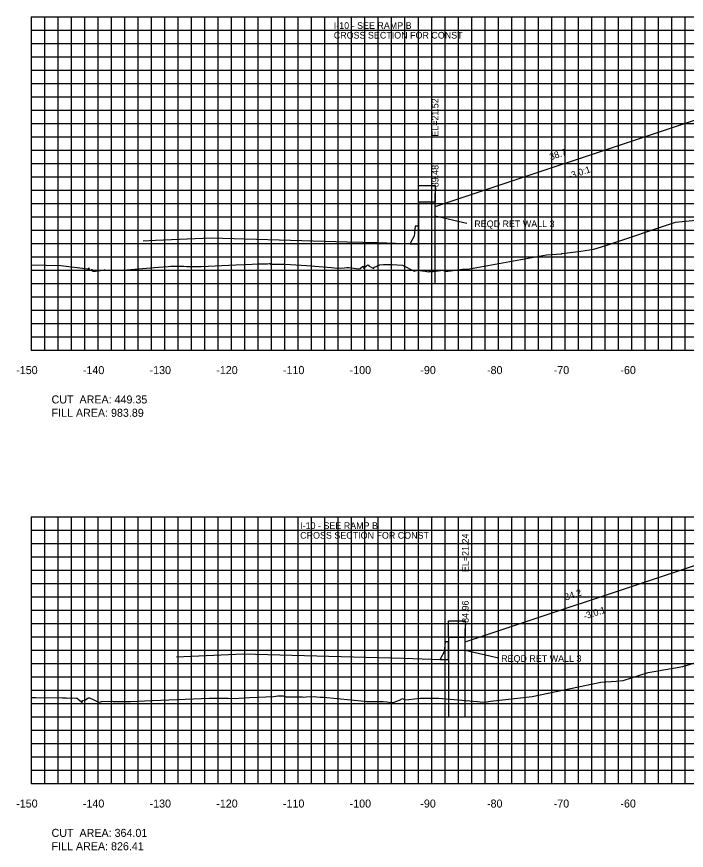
# Model space of a CAD drawing. Extents: x 1800880 to 1814006, y 250083 to 250560.
# Drawn here: x 1808258.8 to 1808359.2, y 250089.4 to 250214.4 of the extents above; entities that cross this region are included whole.
import ezdxf

# ---------------------------------------------------------------- set-up
doc = ezdxf.new("R2010")
doc.units = 0
for name, color, linetype in [('ANNO-TXT', 7, 'Continuous'), ('CL-CNST', 7, 'Continuous'), ('Default', 7, 'Continuous'), ('DESIGN - DRAINAGE - Bridges', 7, 'Continuous'), ('DRAINAGETXT', 7, 'Continuous'), ('EPTEXT', 7, 'Continuous'), ('Level 37', 7, 'Continuous'), ('Level 46', 7, 'Continuous'), ('Level 62', 7, 'Continuous'), ('SHT-BDR', 7, 'Continuous')]:
    doc.layers.add(name, color=color, linetype=linetype)

msp = doc.modelspace()

# ---------------------------------------------------------------- linework, layer by layer
at = {"layer": 'CL-CNST'}
for points in [[(1808261, 250177.21), (1808265.39, 250177.13), (1808269.46, 250176.6), (1808269.6, 250176.52), (1808269.61, 250176.77), (1808269.64, 250176.5), (1808269.64, 250176.54), (1808269.67, 250176.5), (1808269.71, 250176.44), (1808269.73, 250176.42), (1808269.78, 250176.43), (1808269.84, 250176.42), (1808269.89, 250176.4), (1808269.93, 250176.38), (1808270.04, 250176.55), (1808270.09, 250176.28), (1808270.13, 250176.32), (1808270.14, 250176.32), (1808270.15, 250176.27), (1808270.17, 250176.28), (1808270.25, 250176.25), (1808270.43, 250176.28), (1808270.57, 250176.27), (1808271.67, 250176.43), (1808271.89, 250176.47), (1808272, 250176.45), (1808272.22, 250176.44), (1808272.42, 250176.42), (1808273.38, 250176.43), (1808274.69, 250176.44), (1808280.03, 250176.88), (1808281.49, 250176.99), (1808281.82, 250177), (1808283.86, 250177), (1808284.25, 250176.96), (1808284.27, 250176.96), (1808284.36, 250176.96), (1808286.45, 250176.99), (1808291.62, 250177.22), (1808294.07, 250177.33), (1808295.08, 250177.35), (1808296.36, 250177.36), (1808296.61, 250177.43), (1808296.76, 250177.43), (1808296.79, 250177.34), (1808297.6, 250177.34), (1808299.03, 250177.34), (1808302.24, 250177.11), (1808305.96, 250176.84), (1808306.81, 250176.72), (1808307.93, 250176.78), (1808308.29, 250176.83), (1808308.6, 250176.83), (1808309.02, 250176.76), (1808309.96, 250176.64), (1808310.3, 250176.68), (1808310.66, 250177.03), (1808310.89, 250176.79), (1808310.89, 250176.6), (1808310.9, 250176.8), (1808310.92, 250176.84), (1808310.92, 250176.84), (1808311.19, 250177.04), (1808311.29, 250177.12), (1808311.49, 250177.23), (1808311.59, 250177.05), (1808312.26, 250176.68), (1808312.44, 250176.89), (1808313.24, 250177.24), (1808313.78, 250177.26), (1808315.09, 250177.26), (1808316.64, 250177.19), (1808318.37, 250176.26), (1808318.87, 250176.43), (1808320.01, 250176.26), (1808320.25, 250176.21), (1808320.46, 250176.18), (1808320.62, 250176.2), (1808321.22, 250176.24), (1808321.63, 250176.27), (1808322.69, 250176.42), (1808322.97, 250176.28), (1808323.07, 250176.24), (1808325.63, 250176.57), (1808326.67, 250176.63), (1808338.24, 250178.72), (1808340.45, 250178.89), (1808340.5, 250178.92), (1808340.57, 250178.93), (1808343.37, 250179.29), (1808345.32, 250179.55), (1808347.14, 250180.1), (1808357.54, 250183.62), (1808361.13, 250183.99)], [(1808261, 250112.34), (1808261.65, 250112.33), (1808265.61, 250112.26), (1808266.15, 250112.26), (1808266.17, 250112.24), (1808266.82, 250112.27), (1808267.05, 250112.27), (1808267.1, 250112.27), (1808267.11, 250112.27), (1808267.5, 250112.24), (1808267.64, 250112.26), (1808267.75, 250112.25), (1808267.84, 250112.24), (1808267.95, 250112.15), (1808268.48, 250111.69), (1808268.61, 250111.49), (1808268.64, 250111.9), (1808269.07, 250111.99), (1808269.47, 250112.26), (1808269.69, 250112.26), (1808270.33, 250111.98), (1808270.85, 250111.74), (1808271.18, 250111.62), (1808271.5, 250111.72), (1808273.14, 250111.79), (1808273.26, 250111.75), (1808275.28, 250111.74), (1808275.86, 250111.74), (1808277.92, 250111.83), (1808286.49, 250112.19), (1808287.62, 250112.21), (1808288.73, 250112.22), (1808289.03, 250112.22), (1808290.47, 250112.21), (1808291.55, 250112.2), (1808292.1, 250112.23), (1808293.68, 250112.35), (1808297.32, 250112.48), (1808297.91, 250112.57), (1808298.68, 250112.59), (1808298.74, 250112.58), (1808299.2, 250112.41), (1808299.61, 250112.45), (1808301.6, 250112.43), (1808301.72, 250112.4), (1808302.17, 250112.42), (1808303.5, 250112.47), (1808303.77, 250112.42), (1808304.26, 250112.4), (1808304.77, 250112.4), (1808310.92, 250111.78), (1808311.23, 250111.74), (1808311.43, 250111.74), (1808311.65, 250111.74), (1808312.25, 250111.74), (1808313.75, 250111.74), (1808314.29, 250111.68), (1808314.65, 250111.65), (1808315, 250111.6), (1808315.38, 250111.65), (1808316.19, 250111.94), (1808316.61, 250112.19), (1808316.99, 250112), (1808317.6, 250112.01), (1808319.27, 250112.23), (1808320.19, 250112.23), (1808320.89, 250112.23), (1808322, 250112.25), (1808327.89, 250111.72), (1808328.26, 250111.7), (1808328.92, 250111.64), (1808329.8, 250111.8), (1808334.31, 250112.3), (1808336.08, 250112.5), (1808346.36, 250114.64), (1808348.65, 250114.8), (1808349.71, 250114.87), (1808353.44, 250116.07), (1808355.78, 250116.48), (1808358.66, 250116.98), (1808364.9, 250118.86)]]:
    msp.add_lwpolyline(points, dxfattribs=at)
at = {"layer": 'Default'}
for p, q in [((1808319.03, 250180.37), (1808319.03, 250183.04)), ((1808323.54, 250118.02), (1808323.54, 250120.69))]:
    msp.add_line(p, q, dxfattribs=at)
for points in [[(1808319.03, 250183.04), (1808318.53, 250183.04), (1808318.35, 250181.54), (1808317.8, 250180.54), (1808317.78, 250180.37), (1808319.03, 250180.37)], [(1808323.54, 250120.69), (1808323.04, 250120.69), (1808322.86, 250119.19), (1808322.31, 250118.19), (1808322.29, 250118.02), (1808323.54, 250118.02)]]:
    msp.add_lwpolyline(points, dxfattribs=at)
at = {"layer": 'DESIGN - DRAINAGE - Bridges'}
for p, q in [((1808260.94, 250214.43), (1808261, 250214.43)), ((1808261, 250164.43), (1808261, 250214.43)), ((1808260.94, 250204.43), (1808261, 250204.43)), ((1808260.94, 250194.43), (1808261, 250194.43)), ((1808260.94, 250184.43), (1808261, 250184.43)), ((1808260.94, 250174.43), (1808261, 250174.43)), ((1808260.94, 250164.43), (1808261, 250164.43)), ((1808261, 250164.43), (1808561, 250164.43)), ((1808261, 250164.37), (1808261, 250164.43)), ((1808271, 250164.37), (1808271, 250164.43)), ((1808281, 250164.37), (1808281, 250164.43)), ((1808291, 250164.37), (1808291, 250164.43)), ((1808301, 250164.37), (1808301, 250164.43)), ((1808311, 250164.37), (1808311, 250164.43)), ((1808321, 250164.37), (1808321, 250164.43)), ((1808331, 250164.37), (1808331, 250164.43)), ((1808341, 250164.37), (1808341, 250164.43)), ((1808351, 250164.37), (1808351, 250164.43)), ((1808260.94, 250139.43), (1808261, 250139.43)), ((1808261, 250099.43), (1808261, 250139.43)), ((1808260.94, 250129.43), (1808261, 250129.43)), ((1808260.94, 250119.43), (1808261, 250119.43)), ((1808260.94, 250109.43), (1808261, 250109.43)), ((1808260.94, 250099.43), (1808261, 250099.43)), ((1808261, 250099.43), (1808561, 250099.43)), ((1808261, 250099.37), (1808261, 250099.43)), ((1808271, 250099.37), (1808271, 250099.43)), ((1808281, 250099.37), (1808281, 250099.43)), ((1808291, 250099.37), (1808291, 250099.43)), ((1808301, 250099.37), (1808301, 250099.43)), ((1808311, 250099.37), (1808311, 250099.43)), ((1808321, 250099.37), (1808321, 250099.43)), ((1808331, 250099.37), (1808331, 250099.43)), ((1808341, 250099.37), (1808341, 250099.43)), ((1808351, 250099.37), (1808351, 250099.43))]:
    msp.add_line(p, q, dxfattribs=at)
at = {"layer": 'EPTEXT'}
for p, q in [((1808326.25, 250183.43), (1808321.53, 250184.53)), ((1808331.04, 250118.23), (1808326.04, 250119.4))]:
    msp.add_line(p, q, dxfattribs=at)
at = {"layer": 'Level 37'}
for p, q in [((1808321.52, 250185.96), (1808321.52, 250187.96)), ((1808326.04, 250120.67), (1808326.04, 250122.67))]:
    msp.add_line(p, q, dxfattribs=at)
at = {"layer": 'Level 46'}
for p, q in [((1808261, 250214.43), (1808561, 250214.43)), ((1808261, 250164.43), (1808261, 250214.43)), ((1808263, 250164.43), (1808263, 250214.43)), ((1808265, 250164.43), (1808265, 250214.43)), ((1808267, 250164.43), (1808267, 250214.43)), ((1808269, 250164.43), (1808269, 250214.43)), ((1808271, 250164.43), (1808271, 250214.43)), ((1808273, 250164.43), (1808273, 250214.43)), ((1808275, 250164.43), (1808275, 250214.43)), ((1808277, 250164.43), (1808277, 250214.43)), ((1808279, 250164.43), (1808279, 250214.43)), ((1808281, 250164.43), (1808281, 250214.43)), ((1808283, 250164.43), (1808283, 250214.43)), ((1808285, 250164.43), (1808285, 250214.43)), ((1808287, 250164.43), (1808287, 250214.43)), ((1808289, 250164.43), (1808289, 250214.43)), ((1808291, 250164.43), (1808291, 250214.43)), ((1808293, 250164.43), (1808293, 250214.43)), ((1808295, 250164.43), (1808295, 250214.43)), ((1808297, 250164.43), (1808297, 250214.43)), ((1808299, 250164.43), (1808299, 250214.43)), ((1808301, 250164.43), (1808301, 250214.43)), ((1808303, 250164.43), (1808303, 250214.43)), ((1808305, 250164.43), (1808305, 250214.43)), ((1808307, 250164.43), (1808307, 250214.43)), ((1808309, 250164.43), (1808309, 250214.43)), ((1808311, 250164.43), (1808311, 250214.43)), ((1808313, 250164.43), (1808313, 250214.43)), ((1808315, 250164.43), (1808315, 250214.43)), ((1808317, 250164.43), (1808317, 250214.43)), ((1808319, 250164.43), (1808319, 250214.43)), ((1808321, 250164.43), (1808321, 250214.43)), ((1808323, 250164.43), (1808323, 250214.43)), ((1808325, 250164.43), (1808325, 250214.43)), ((1808327, 250164.43), (1808327, 250214.43)), ((1808329, 250164.43), (1808329, 250214.43)), ((1808331, 250164.43), (1808331, 250214.43)), ((1808333, 250164.43), (1808333, 250214.43)), ((1808335, 250164.43), (1808335, 250214.43)), ((1808337, 250164.43), (1808337, 250214.43)), ((1808339, 250164.43), (1808339, 250214.43)), ((1808341, 250164.43), (1808341, 250214.43)), ((1808343, 250164.43), (1808343, 250214.43)), ((1808345, 250164.43), (1808345, 250214.43)), ((1808347, 250164.43), (1808347, 250214.43)), ((1808349, 250164.43), (1808349, 250214.43)), ((1808351, 250164.43), (1808351, 250214.43)), ((1808353, 250164.43), (1808353, 250214.43)), ((1808355, 250164.43), (1808355, 250214.43)), ((1808357, 250164.43), (1808357, 250214.43)), ((1808359, 250164.43), (1808359, 250214.43)), ((1808261, 250212.43), (1808561, 250212.43)), ((1808261, 250210.43), (1808561, 250210.43)), ((1808261, 250208.43), (1808561, 250208.43)), ((1808261, 250206.43), (1808561, 250206.43)), ((1808261, 250204.43), (1808561, 250204.43)), ((1808261, 250202.43), (1808561, 250202.43)), ((1808261, 250200.43), (1808561, 250200.43)), ((1808261, 250198.43), (1808561, 250198.43)), ((1808261, 250196.43), (1808561, 250196.43)), ((1808261, 250194.43), (1808561, 250194.43)), ((1808261, 250192.43), (1808561, 250192.43)), ((1808261, 250190.43), (1808561, 250190.43)), ((1808261, 250188.43), (1808561, 250188.43)), ((1808261, 250186.43), (1808561, 250186.43)), ((1808261, 250184.43), (1808561, 250184.43)), ((1808261, 250182.43), (1808561, 250182.43)), ((1808261, 250180.43), (1808561, 250180.43)), ((1808261, 250178.43), (1808561, 250178.43)), ((1808261, 250176.43), (1808561, 250176.43)), ((1808261, 250174.43), (1808561, 250174.43)), ((1808261, 250172.43), (1808561, 250172.43)), ((1808261, 250170.43), (1808561, 250170.43)), ((1808261, 250168.43), (1808561, 250168.43)), ((1808261, 250166.43), (1808561, 250166.43)), ((1808261, 250164.43), (1808561, 250164.43)), ((1808261, 250139.43), (1808561, 250139.43)), ((1808261, 250099.43), (1808261, 250139.43)), ((1808263, 250099.43), (1808263, 250139.43)), ((1808265, 250099.43), (1808265, 250139.43)), ((1808267, 250099.43), (1808267, 250139.43)), ((1808269, 250099.43), (1808269, 250139.43)), ((1808271, 250099.43), (1808271, 250139.43)), ((1808273, 250099.43), (1808273, 250139.43)), ((1808275, 250099.43), (1808275, 250139.43)), ((1808277, 250099.43), (1808277, 250139.43)), ((1808279, 250099.43), (1808279, 250139.43)), ((1808281, 250099.43), (1808281, 250139.43)), ((1808283, 250099.43), (1808283, 250139.43)), ((1808285, 250099.43), (1808285, 250139.43)), ((1808287, 250099.43), (1808287, 250139.43)), ((1808289, 250099.43), (1808289, 250139.43)), ((1808291, 250099.43), (1808291, 250139.43)), ((1808293, 250099.43), (1808293, 250139.43)), ((1808295, 250099.43), (1808295, 250139.43)), ((1808297, 250099.43), (1808297, 250139.43)), ((1808299, 250099.43), (1808299, 250139.43)), ((1808301, 250099.43), (1808301, 250139.43)), ((1808303, 250099.43), (1808303, 250139.43)), ((1808305, 250099.43), (1808305, 250139.43)), ((1808307, 250099.43), (1808307, 250139.43)), ((1808309, 250099.43), (1808309, 250139.43)), ((1808311, 250099.43), (1808311, 250139.43)), ((1808313, 250099.43), (1808313, 250139.43)), ((1808315, 250099.43), (1808315, 250139.43)), ((1808317, 250099.43), (1808317, 250139.43)), ((1808319, 250099.43), (1808319, 250139.43)), ((1808321, 250099.43), (1808321, 250139.43)), ((1808323, 250099.43), (1808323, 250139.43)), ((1808325, 250099.43), (1808325, 250139.43)), ((1808327, 250099.43), (1808327, 250139.43)), ((1808329, 250099.43), (1808329, 250139.43)), ((1808331, 250099.43), (1808331, 250139.43)), ((1808333, 250099.43), (1808333, 250139.43)), ((1808335, 250099.43), (1808335, 250139.43)), ((1808337, 250099.43), (1808337, 250139.43)), ((1808339, 250099.43), (1808339, 250139.43)), ((1808341, 250099.43), (1808341, 250139.43)), ((1808343, 250099.43), (1808343, 250139.43)), ((1808345, 250099.43), (1808345, 250139.43)), ((1808347, 250099.43), (1808347, 250139.43)), ((1808349, 250099.43), (1808349, 250139.43)), ((1808351, 250099.43), (1808351, 250139.43)), ((1808353, 250099.43), (1808353, 250139.43)), ((1808355, 250099.43), (1808355, 250139.43)), ((1808357, 250099.43), (1808357, 250139.43)), ((1808359, 250099.43), (1808359, 250139.43)), ((1808261, 250137.43), (1808561, 250137.43)), ((1808261, 250135.43), (1808561, 250135.43)), ((1808261, 250133.43), (1808561, 250133.43)), ((1808261, 250131.43), (1808561, 250131.43)), ((1808261, 250129.43), (1808561, 250129.43)), ((1808261, 250127.43), (1808561, 250127.43)), ((1808261, 250125.43), (1808561, 250125.43)), ((1808261, 250123.43), (1808561, 250123.43)), ((1808261, 250121.43), (1808561, 250121.43)), ((1808261, 250119.43), (1808561, 250119.43)), ((1808261, 250117.43), (1808561, 250117.43)), ((1808261, 250115.43), (1808561, 250115.43)), ((1808261, 250113.43), (1808561, 250113.43)), ((1808261, 250111.43), (1808561, 250111.43)), ((1808261, 250109.43), (1808561, 250109.43)), ((1808261, 250107.43), (1808561, 250107.43)), ((1808261, 250105.43), (1808561, 250105.43)), ((1808261, 250103.43), (1808561, 250103.43)), ((1808261, 250101.43), (1808561, 250101.43)), ((1808261, 250099.43), (1808561, 250099.43))]:
    msp.add_line(p, q, dxfattribs=at)
at = {"layer": 'Level 62'}
for points in [[(1808321.52, 250185.96), (1808360.25, 250198.87), (1808363.75, 250199.01), (1808365.75, 250199.09), (1808374.68, 250199.44), (1808374.75, 250199.52), (1808375.75, 250199.56), (1808387.75, 250199.82), (1808399.75, 250199.56), (1808409.75, 250199.16), (1808412.25, 250198.97), (1808426.88, 250199.56), (1808438.88, 250199.82), (1808443.5, 250199.72), (1808455.51, 250199.45), (1808456.5, 250199.41), (1808456.58, 250199.34), (1808465.51, 250198.98), (1808467.51, 250198.9), (1808471.01, 250198.76), (1808524.66, 250180.88), (1808529.16, 250180.88)], [(1808277.76, 250180.83), (1808279.61, 250180.9), (1808287.94, 250181.25), (1808308.32, 250180.68), (1808313.05, 250180.55), (1808318.14, 250180.36), (1808319.03, 250180.32)], [(1808326.04, 250120.67), (1808360.25, 250132.08), (1808363.75, 250132.22), (1808365.75, 250132.3), (1808374.68, 250132.65), (1808374.75, 250132.73), (1808375.75, 250132.77), (1808387.75, 250132.81), (1808399.75, 250132.54), (1808409.75, 250132.14), (1808412.25, 250132.13), (1808428.1, 250132.77), (1808440.1, 250132.81), (1808445.94, 250132.68), (1808457.94, 250132.41), (1808458.94, 250132.37), (1808459.01, 250132.3), (1808467.94, 250131.94), (1808469.94, 250131.86), (1808473.45, 250131.72), (1808518.28, 250116.78), (1808522.78, 250116.78)], [(1808282.72, 250118.43), (1808289.45, 250118.72), (1808292.74, 250118.86), (1808309.3, 250118.43), (1808316.79, 250118.22), (1808320.97, 250118.07), (1808323.54, 250117.97)]]:
    msp.add_lwpolyline(points, dxfattribs=at)
for points in [[(1808321.53, 250186.62), (1808319.03, 250186.62), (1808319.03, 250189.12), (1808321.53, 250189.12)], [(1808319.03, 250174.43), (1808321.53, 250174.43), (1808321.53, 250186.62), (1808319.03, 250186.62)], [(1808326.04, 250121.33), (1808323.54, 250121.33), (1808323.54, 250123.83), (1808326.04, 250123.83)], [(1808323.54, 250109.43), (1808326.04, 250109.43), (1808326.04, 250121.33), (1808323.54, 250121.33)]]:
    msp.add_lwpolyline(points, close=True, dxfattribs=at)

# ---------------------------------------------------------------- texts
for s, p in [('-150', (1808258.7, 250160.83)), ('-140', (1808268.7, 250160.83)), ('-130', (1808278.7, 250160.83)), ('-120', (1808288.7, 250160.83)), ('-110', (1808298.7, 250160.83)), ('-100', (1808308.7, 250160.83)), ('-90', (1808319.3, 250160.83)), ('-80', (1808329.3, 250160.83)), ('-70', (1808339.3, 250160.83)), ('-60', (1808349.3, 250160.83)), ('-150', (1808258.7, 250095.83)), ('-140', (1808268.7, 250095.83)), ('-130', (1808278.7, 250095.83)), ('-120', (1808288.7, 250095.83)), ('-110', (1808298.7, 250095.83)), ('-100', (1808308.7, 250095.83)), ('-90', (1808319.3, 250095.83)), ('-80', (1808329.3, 250095.83)), ('-70', (1808339.3, 250095.83)), ('-60', (1808349.3, 250095.83))]:
    msp.add_text(s, height=1.2).set_placement(p)
at = {"layer": 'ANNO-TXT'}
for s, p in [('38.7', (1808338.85, 250192.89)), ('34.2', (1808341.11, 250126.86))]:
    msp.add_text(s, height=1, rotation=18.4348, dxfattribs=at).set_placement(p)
at = {"layer": 'DESIGN - DRAINAGE - Bridges'}
for p in [(1808261, 250164.43), (1808261, 250099.43)]:
    msp.add_text('-', height=0.0001, dxfattribs=at).set_placement(p)
at = {"layer": 'DRAINAGETXT'}
for s, p in [('CUT  AREA: 449.35', (1808264, 250156.43)), ('FILL AREA: 983.89', (1808264, 250154.43)), ('CUT  AREA: 364.01', (1808264, 250091.43)), ('FILL AREA: 826.41', (1808264, 250089.43))]:
    msp.add_text(s, height=1.2, dxfattribs=at).set_placement(p)
at = {"layer": 'EPTEXT'}
for s, p in [('I-10 - SEE RAMP B', (1808306.32, 250212.6)), ('CROSS SECTION FOR CONST ', (1808306.32, 250211.15)), ('REQD RET WALL 3', (1808327.39, 250182.87)), ('I-10 - SEE RAMP B', (1808301.28, 250137.6)), ('CROSS SECTION FOR CONST ', (1808301.28, 250136.15)), ('REQD RET WALL 3', (1808331.42, 250117.68))]:
    msp.add_text(s, height=1, dxfattribs=at).set_placement(p)
at = {"layer": 'Level 37'}
for p in [(1808341.68, 250190.04), (1808343.94, 250124)]:
    msp.add_text('-3.0:1', height=1, rotation=18.4348, dxfattribs=at).set_placement(p)
at = {"layer": 'SHT-BDR'}
for s, p in [('EL=21.52', (1808322.02, 250196.43)), ('-89.48', (1808322.02, 250188.41)), ('EL=21.24', (1808326.54, 250131.15)), ('-84.96', (1808326.54, 250123.08))]:
    msp.add_text(s, height=1, rotation=90, dxfattribs=at).set_placement(p)

doc.saveas('drawing.dxf')
